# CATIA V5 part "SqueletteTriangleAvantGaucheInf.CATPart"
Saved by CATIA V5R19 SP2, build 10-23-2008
Part number: SqueletteTriangleAvantGaucheInf
Bounding box of the stored display mesh (mm): x 617.517 to 667.517, y -148.642 to -59.099, z -240.762 to -220.798
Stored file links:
  D:\Mes Documents\ressource\CATIA\Ensemble Catia\Voiture_Telecommmande\SchemaCinematiqueFinal\SqueletteTriangleAvantGaucheInf.CATPart
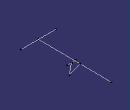
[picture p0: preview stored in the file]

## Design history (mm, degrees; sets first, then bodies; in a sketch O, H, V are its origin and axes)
AxisSystem1: origin (0, 0, 0), X (1, 0, 0), Y (0, 1, 0), Z (0, 0, 1)
Set1
  Point1 to Point6: stored without definition
  Line1: stored without definition
  Point7: stored without definition
  Line2: stored without definition
  Point8: stored without definition
  Point9: stored without definition
  Line3 to Line6: stored without definition
Body1 (main body)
